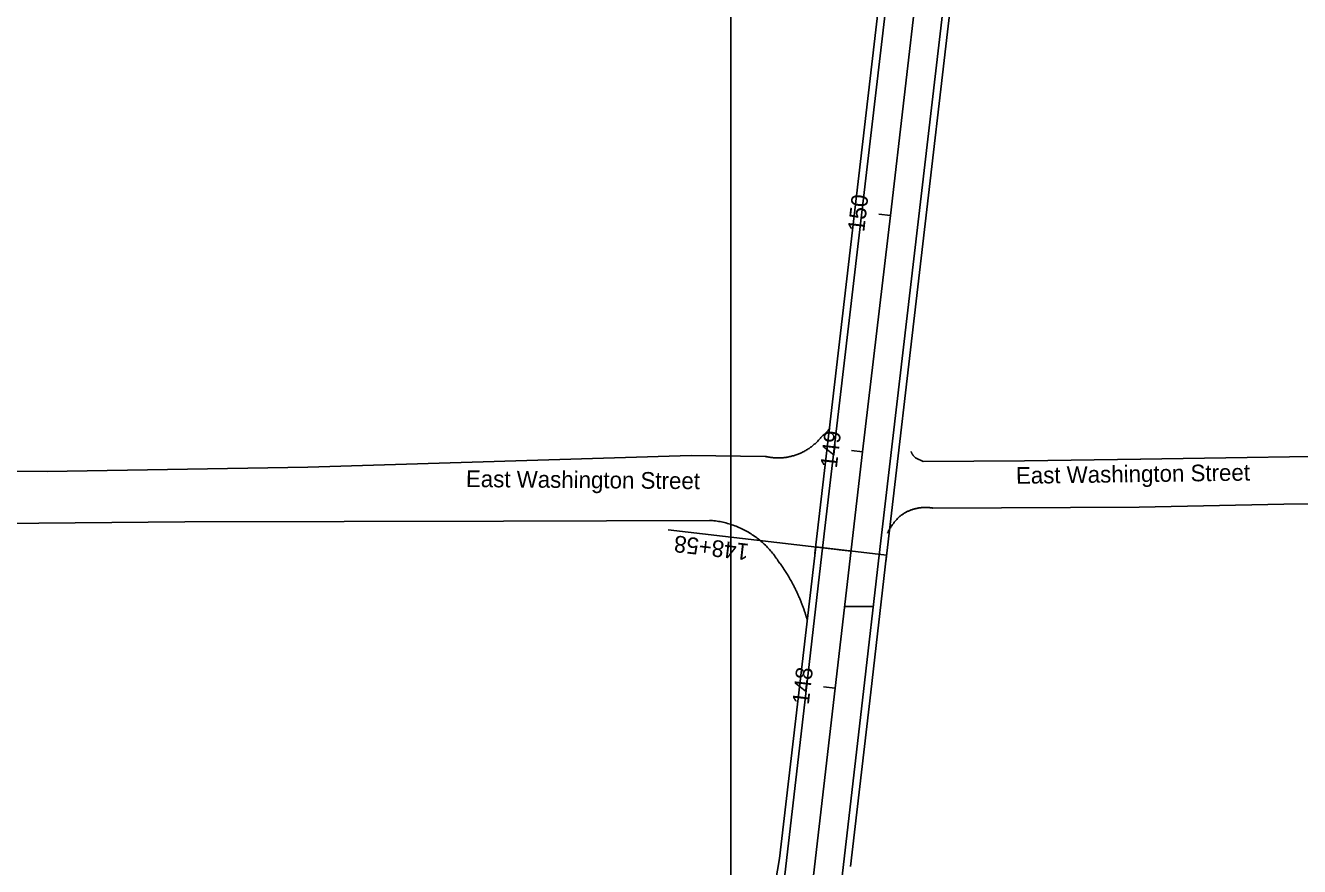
# Model space of a CAD drawing. Extents: x 2318076 to 2324211, y 613525 to 630327.
# Drawn here: x 2320373 to 2320909, y 629287 to 629641 of the extents above; entities that cross this region are included whole.
import ezdxf

# ---------------------------------------------------------------- set-up
doc = ezdxf.new("R2010")
doc.units = 0
for name, color, linetype in [('GE_P_CL_50', 7, 'Continuous'), ('PV_P_EOP', 7, 'Continuous'), ('PV_P_Shoulder', 7, 'Continuous'), ('PV_X_Shoulder', 7, 'Continuous'), ('RS_Raster1', 7, 'Continuous'), ('SC_Scratch1', 7, 'Continuous'), ('SC_Scratch3', 7, 'Continuous')]:
    doc.layers.add(name, color=color, linetype=linetype)

msp = doc.modelspace()

# ---------------------------------------------------------------- linework, layer by layer
at = {"layer": 'GE_P_CL_50'}
for p, q in [((2320736.97, 629561.09), (2320732.1, 629561.66)), ((2320725.26, 629461.78), (2320720.57, 629462.32)), ((2320720.43, 629420.06), (2320643.58, 629428.97)), ((2320720.41, 629420.07), (2320715.44, 629420.64)), ((2320713.75, 629362.45), (2320708.79, 629363.02))]:
    msp.add_line(p, q, dxfattribs=at)
msp.add_lwpolyline([(2320476.3, 627307.7), (2320485.22, 627375.57), (2320502.11, 627520.92), (2320519.22, 627676.47), (2320531.82, 627783.89), (2320546.8, 627927.12), (2320554.45, 627991.34), (2320572.51, 628138.41), (2320649.52, 628804.84), (2320678.77, 629064.5), (2320690.76, 629163.78), (2320713.75, 629362.45), (2320725.26, 629461.78), (2320736.97, 629561.09), (2320748.4, 629660.43), (2320759.09, 629759.86), (2320769.62, 629859.3), (2320777.51, 629931.12), (2320778.25, 629937.84)], dxfattribs=at)
at = {"layer": 'PV_P_EOP'}
for p, q in [((2320747.44, 629459.26), (2320747.75, 629459.13)), ((2320705.53, 629421.79), (2320735.33, 629418.34))]:
    msp.add_line(p, q, dxfattribs=at)
for points in [[(2320707.99, 629468.12), (2320708.36, 629468.42), (2320708.72, 629468.73), (2320709.08, 629469.05), (2320709.43, 629469.37), (2320709.78, 629469.7), (2320710.12, 629470.04), (2320710.45, 629470.38), (2320710.78, 629470.72), (2320711.1, 629471.08), (2320711.42, 629471.43), (2320711.58, 629471.62)], [(2320679.85, 629173.88), (2320701.83, 629363.83), (2320708.13, 629418.9), (2320708.13, 629418.9)], [(2320704.21, 629175.59), (2320725.67, 629361.07), (2320731.95, 629415.91), (2320731.95, 629415.91)]]:
    msp.add_lwpolyline(points, dxfattribs=at)
at = {"layer": 'PV_P_Shoulder'}
msp.add_line((2320669.97, 629175.43), (2320690.38, 629290.93), dxfattribs=at)
for points in [[(2320690.38, 629290.93), (2320698.85, 629364.17), (2320705.53, 629421.79)], [(2320720.18, 629287.5), (2320728.65, 629360.72), (2320735.33, 629418.34)]]:
    msp.add_lwpolyline(points, dxfattribs=at)
at = {"layer": 'PV_X_Shoulder'}
for points in [[(2320705.21, 629419), (2320733.49, 629662.09), (2320744.17, 629761.45), (2320754.71, 629860.91), (2320762.6, 629932.76), (2320763.34, 629939.48)], [(2320735.01, 629415.55), (2320763.31, 629658.77), (2320774, 629758.27), (2320784.54, 629857.69), (2320792.42, 629929.48), (2320793.16, 629936.2)]]:
    msp.add_lwpolyline(points, dxfattribs=at)
at = {"layer": 'RS_Raster1'}
msp.add_line((2320841.5, 629438.56), (2320754.79, 629438.1), dxfattribs=at)
for points in [[(2320708.13, 629418.9), (2320736.47, 629661.76), (2320747.15, 629761.13), (2320757.69, 629860.59), (2320765.58, 629932.43), (2320766.32, 629939.15)], [(2320731.95, 629415.91), (2320760.33, 629659.11), (2320771.02, 629758.59), (2320781.55, 629858.02), (2320789.44, 629929.81), (2320790.18, 629936.53)], [(2322566.94, 629479.72), (2322351.65, 629476.68), (2322140.39, 629474.14), (2321926.11, 629471.53), (2321678.25, 629469.05), (2321429.71, 629465.5), (2321192.6, 629463.24), (2320949.44, 629460.28), (2320842.07, 629458.72)], [(2320707.99, 629468.12), (2320708.36, 629468.42), (2320708.72, 629468.73), (2320709.08, 629469.05), (2320709.43, 629469.37), (2320709.78, 629469.7), (2320710.12, 629470.04), (2320710.45, 629470.38), (2320710.78, 629470.72), (2320711.1, 629471.08), (2320711.42, 629471.43), (2320711.58, 629471.62)], [(2320684.27, 629459.85), (2320684.66, 629459.76), (2320685.05, 629459.67), (2320685.45, 629459.59), (2320685.84, 629459.52), (2320686.24, 629459.46), (2320686.64, 629459.4), (2320687.04, 629459.35), (2320687.44, 629459.31), (2320687.84, 629459.27), (2320688.24, 629459.24), (2320688.64, 629459.22), (2320689.04, 629459.2), (2320689.44, 629459.19), (2320689.84, 629459.19), (2320690.25, 629459.2), (2320690.65, 629459.21), (2320691.05, 629459.23), (2320691.45, 629459.26), (2320691.85, 629459.29), (2320692.25, 629459.33), (2320692.65, 629459.38), (2320693.05, 629459.43), (2320693.45, 629459.49), (2320693.84, 629459.56), (2320694.24, 629459.64), (2320694.63, 629459.72), (2320695.02, 629459.81), (2320695.42, 629459.9), (2320695.8, 629460), (2320696.19, 629460.11), (2320696.58, 629460.23), (2320696.96, 629460.35), (2320697.34, 629460.48), (2320697.72, 629460.62), (2320698.1, 629460.76), (2320698.47, 629460.91), (2320698.84, 629461.06), (2320699.21, 629461.23), (2320699.58, 629461.39), (2320699.94, 629461.57), (2320700.3, 629461.75), (2320700.66, 629461.94), (2320701.01, 629462.13), (2320701.36, 629462.33), (2320701.7, 629462.53), (2320702.05, 629462.75), (2320702.39, 629462.96), (2320702.72, 629463.19), (2320703.05, 629463.41), (2320703.38, 629463.65), (2320703.7, 629463.89), (2320704.02, 629464.14), (2320704.34, 629464.39), (2320704.65, 629464.64), (2320704.95, 629464.91), (2320705.25, 629465.17), (2320705.55, 629465.45), (2320705.84, 629465.72), (2320706.13, 629466.01), (2320706.41, 629466.29), (2320706.69, 629466.59), (2320706.96, 629466.88), (2320707.22, 629467.19), (2320707.48, 629467.49), (2320707.74, 629467.8), (2320707.99, 629468.12)], [(2319842.85, 629447.56), (2319958.85, 629449.26), (2320053.94, 629450.97), (2320137.26, 629451.41), (2320227.99, 629452.77), (2320303.35, 629453.56), (2320382.52, 629453.53), (2320492.19, 629455.24), (2320653.24, 629460.17), (2320684.27, 629459.85)], [(2320745.65, 629461.85), (2320745.67, 629461.77), (2320745.7, 629461.69), (2320745.73, 629461.62), (2320745.75, 629461.54), (2320745.78, 629461.46), (2320745.81, 629461.39), (2320745.85, 629461.31), (2320745.88, 629461.24), (2320745.91, 629461.16), (2320745.95, 629461.09), (2320745.99, 629461.02), (2320746.02, 629460.94), (2320746.06, 629460.87), (2320746.1, 629460.8), (2320746.15, 629460.73), (2320746.19, 629460.66), (2320746.23, 629460.59), (2320746.28, 629460.53), (2320746.32, 629460.46), (2320746.37, 629460.39), (2320746.42, 629460.33), (2320746.47, 629460.26), (2320746.52, 629460.2), (2320746.57, 629460.13), (2320746.63, 629460.07), (2320746.68, 629460.01), (2320746.74, 629459.95), (2320746.79, 629459.89), (2320746.85, 629459.83), (2320747.44, 629459.26)], [(2320747.75, 629459.13), (2320750.68, 629457.71), (2320793.25, 629457.96), (2320842.1, 629458.72)], [(2322565.73, 629458.91), (2322455.24, 629458), (2322329.32, 629458.43), (2322171.68, 629455.87), (2322013.49, 629454.1), (2321831.46, 629451.91), (2321642.26, 629450.16), (2321452.49, 629446.74), (2321289.49, 629445.15), (2321104.08, 629442.45), (2320902.23, 629439.77), (2320841.5, 629438.56)], [(2320754.79, 629438.1), (2320754.5, 629438.15), (2320754.2, 629438.2), (2320753.9, 629438.24), (2320753.61, 629438.28), (2320753.31, 629438.31), (2320753.01, 629438.33), (2320752.71, 629438.35), (2320752.42, 629438.37), (2320752.12, 629438.38), (2320751.82, 629438.39), (2320751.52, 629438.39), (2320751.22, 629438.38), (2320750.92, 629438.37), (2320750.62, 629438.36), (2320750.33, 629438.34), (2320750.03, 629438.31), (2320749.73, 629438.28), (2320749.43, 629438.24), (2320749.14, 629438.2), (2320748.84, 629438.16), (2320748.55, 629438.11), (2320748.26, 629438.05), (2320747.96, 629437.99), (2320747.67, 629437.92), (2320747.38, 629437.85), (2320747.09, 629437.78), (2320746.8, 629437.7), (2320746.52, 629437.61), (2320746.23, 629437.52), (2320745.95, 629437.42), (2320745.67, 629437.32), (2320745.39, 629437.22), (2320745.11, 629437.11), (2320744.84, 629436.99), (2320744.56, 629436.87), (2320744.29, 629436.75), (2320744.02, 629436.62), (2320743.75, 629436.49), (2320743.49, 629436.35), (2320743.23, 629436.21), (2320742.97, 629436.06), (2320742.71, 629435.91), (2320742.45, 629435.75), (2320742.2, 629435.59), (2320741.95, 629435.43), (2320741.71, 629435.26), (2320741.46, 629435.08), (2320741.22, 629434.91), (2320740.98, 629434.73), (2320740.75, 629434.54)], [(2320660.88, 629432.95), (2320574.31, 629432.6), (2320440.43, 629432.35), (2320286.81, 629430.91), (2320140.72, 629428.3), (2319969.44, 629425.44), (2319838.12, 629424.35)], [(2320689.62, 629416.06), (2320689.27, 629416.6), (2320688.91, 629417.13), (2320688.54, 629417.65), (2320688.16, 629418.17), (2320687.78, 629418.68), (2320687.38, 629419.19), (2320686.98, 629419.68), (2320686.56, 629420.17), (2320686.14, 629420.66), (2320685.71, 629421.13), (2320685.28, 629421.6), (2320684.83, 629422.06), (2320684.38, 629422.51), (2320683.91, 629422.96), (2320683.45, 629423.39), (2320682.97, 629423.82), (2320682.48, 629424.24), (2320681.99, 629424.65), (2320681.49, 629425.06), (2320680.99, 629425.45), (2320680.48, 629425.84), (2320679.96, 629426.21), (2320679.43, 629426.58), (2320678.9, 629426.94), (2320678.36, 629427.28), (2320677.82, 629427.62), (2320677.27, 629427.95), (2320676.72, 629428.27), (2320676.15, 629428.58), (2320675.59, 629428.88), (2320675.02, 629429.17), (2320674.44, 629429.45), (2320673.86, 629429.72), (2320673.28, 629429.98), (2320672.69, 629430.23), (2320672.09, 629430.47), (2320671.49, 629430.7), (2320670.89, 629430.92), (2320670.29, 629431.13), (2320669.68, 629431.33), (2320669.06, 629431.51), (2320668.45, 629431.69), (2320667.83, 629431.85), (2320667.21, 629432.01), (2320666.58, 629432.15), (2320665.96, 629432.29), (2320665.33, 629432.41), (2320664.7, 629432.52), (2320664.06, 629432.62), (2320663.43, 629432.71), (2320662.79, 629432.78), (2320662.16, 629432.85), (2320661.52, 629432.91), (2320660.88, 629432.95)], [(2320740.75, 629434.54), (2320740.46, 629434.26), (2320740.17, 629433.97), (2320739.88, 629433.68), (2320739.61, 629433.38), (2320739.33, 629433.08), (2320739.07, 629432.77), (2320738.8, 629432.46), (2320738.55, 629432.15), (2320738.29, 629431.83), (2320738.05, 629431.5), (2320737.81, 629431.18), (2320737.57, 629430.84), (2320737.34, 629430.51), (2320737.12, 629430.17), (2320736.9, 629429.82), (2320736.69, 629429.47), (2320736.49, 629429.12), (2320736.29, 629428.77), (2320736.1, 629428.41), (2320735.91, 629428.05), (2320735.73, 629427.68), (2320735.71, 629427.64)], [(2320701.97, 629391.11), (2320701.95, 629391.16), (2320701.88, 629391.41), (2320701.81, 629391.66), (2320701.74, 629391.9), (2320701.67, 629392.15), (2320701.59, 629392.4), (2320701.52, 629392.64), (2320701.44, 629392.89), (2320701.37, 629393.13), (2320701.29, 629393.38), (2320701.21, 629393.62), (2320701.13, 629393.86), (2320701.05, 629394.11), (2320700.97, 629394.35), (2320700.89, 629394.6), (2320700.81, 629394.84), (2320700.73, 629395.08), (2320700.64, 629395.32), (2320700.56, 629395.57), (2320700.48, 629395.81), (2320700.39, 629396.05), (2320700.3, 629396.29), (2320700.22, 629396.53), (2320700.13, 629396.77), (2320700.04, 629397.01), (2320699.95, 629397.25), (2320699.86, 629397.49), (2320699.77, 629397.73), (2320699.67, 629397.97), (2320699.58, 629398.21), (2320699.49, 629398.45), (2320699.39, 629398.69), (2320699.29, 629398.93), (2320699.2, 629399.17), (2320699.1, 629399.4), (2320699, 629399.64), (2320698.9, 629399.88), (2320698.8, 629400.11), (2320698.7, 629400.35), (2320698.6, 629400.58), (2320698.5, 629400.82), (2320698.4, 629401.06), (2320698.29, 629401.29), (2320698.19, 629401.52), (2320698.08, 629401.76), (2320697.98, 629401.99), (2320697.87, 629402.22), (2320697.76, 629402.46), (2320697.66, 629402.69), (2320697.55, 629402.92), (2320697.44, 629403.15), (2320697.33, 629403.39), (2320697.21, 629403.62), (2320697.1, 629403.85), (2320696.99, 629404.08), (2320696.87, 629404.31), (2320696.76, 629404.54), (2320696.64, 629404.77), (2320696.53, 629404.99), (2320696.41, 629405.22), (2320696.29, 629405.45), (2320696.18, 629405.68), (2320696.06, 629405.9), (2320695.94, 629406.13), (2320695.82, 629406.36), (2320695.69, 629406.58), (2320695.57, 629406.81), (2320695.45, 629407.03), (2320695.33, 629407.26), (2320695.2, 629407.48), (2320695.08, 629407.71), (2320694.95, 629407.93), (2320694.82, 629408.15), (2320694.69, 629408.37), (2320694.57, 629408.6), (2320694.44, 629408.82), (2320694.31, 629409.04), (2320694.18, 629409.26), (2320694.05, 629409.48), (2320693.91, 629409.7), (2320693.78, 629409.92), (2320693.65, 629410.14), (2320693.51, 629410.35), (2320693.38, 629410.57), (2320693.24, 629410.79), (2320693.11, 629411.01), (2320692.97, 629411.22), (2320692.83, 629411.44), (2320692.69, 629411.65), (2320692.55, 629411.87), (2320692.41, 629412.08), (2320692.27, 629412.3), (2320692.13, 629412.51), (2320691.99, 629412.72), (2320691.85, 629412.94), (2320691.7, 629413.15), (2320691.56, 629413.36), (2320691.41, 629413.57), (2320691.27, 629413.78), (2320691.12, 629413.99), (2320690.98, 629414.2), (2320690.83, 629414.41), (2320690.68, 629414.62), (2320690.53, 629414.82), (2320690.38, 629415.03), (2320690.23, 629415.24), (2320690.08, 629415.44), (2320689.93, 629415.65), (2320689.77, 629415.86), (2320689.62, 629416.06)]]:
    msp.add_lwpolyline(points, dxfattribs=at)
at = {"layer": 'SC_Scratch1'}
msp.add_line((2320717.72, 629396.69), (2320729.89, 629396.69), dxfattribs=at)
at = {"layer": 'SC_Scratch3'}
msp.add_line((2320669.87, 614778.41), (2320669.87, 630327.22), dxfattribs=at)

# ---------------------------------------------------------------- texts
at = {"layer": 'GE_P_CL_50'}
for s, rotation, p in [('150', 83.3814, (2320725.91, 629553.95)), ('149', 83.3814, (2320714.4, 629454.68)), ('East Washington Street', 0.7948, (2320789.72, 629448.3)), ('East Washington Street', 359.4616, (2320558.54, 629446.97)), ('148+58', 173.4076, (2320677.75, 629423.03)), ('148', 83.4076, (2320702.61, 629355.34))]:
    msp.add_text(s, height=7, rotation=rotation, dxfattribs=at).set_placement(p)

doc.saveas('drawing.dxf')
